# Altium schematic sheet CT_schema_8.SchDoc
size 372 x 336 mm
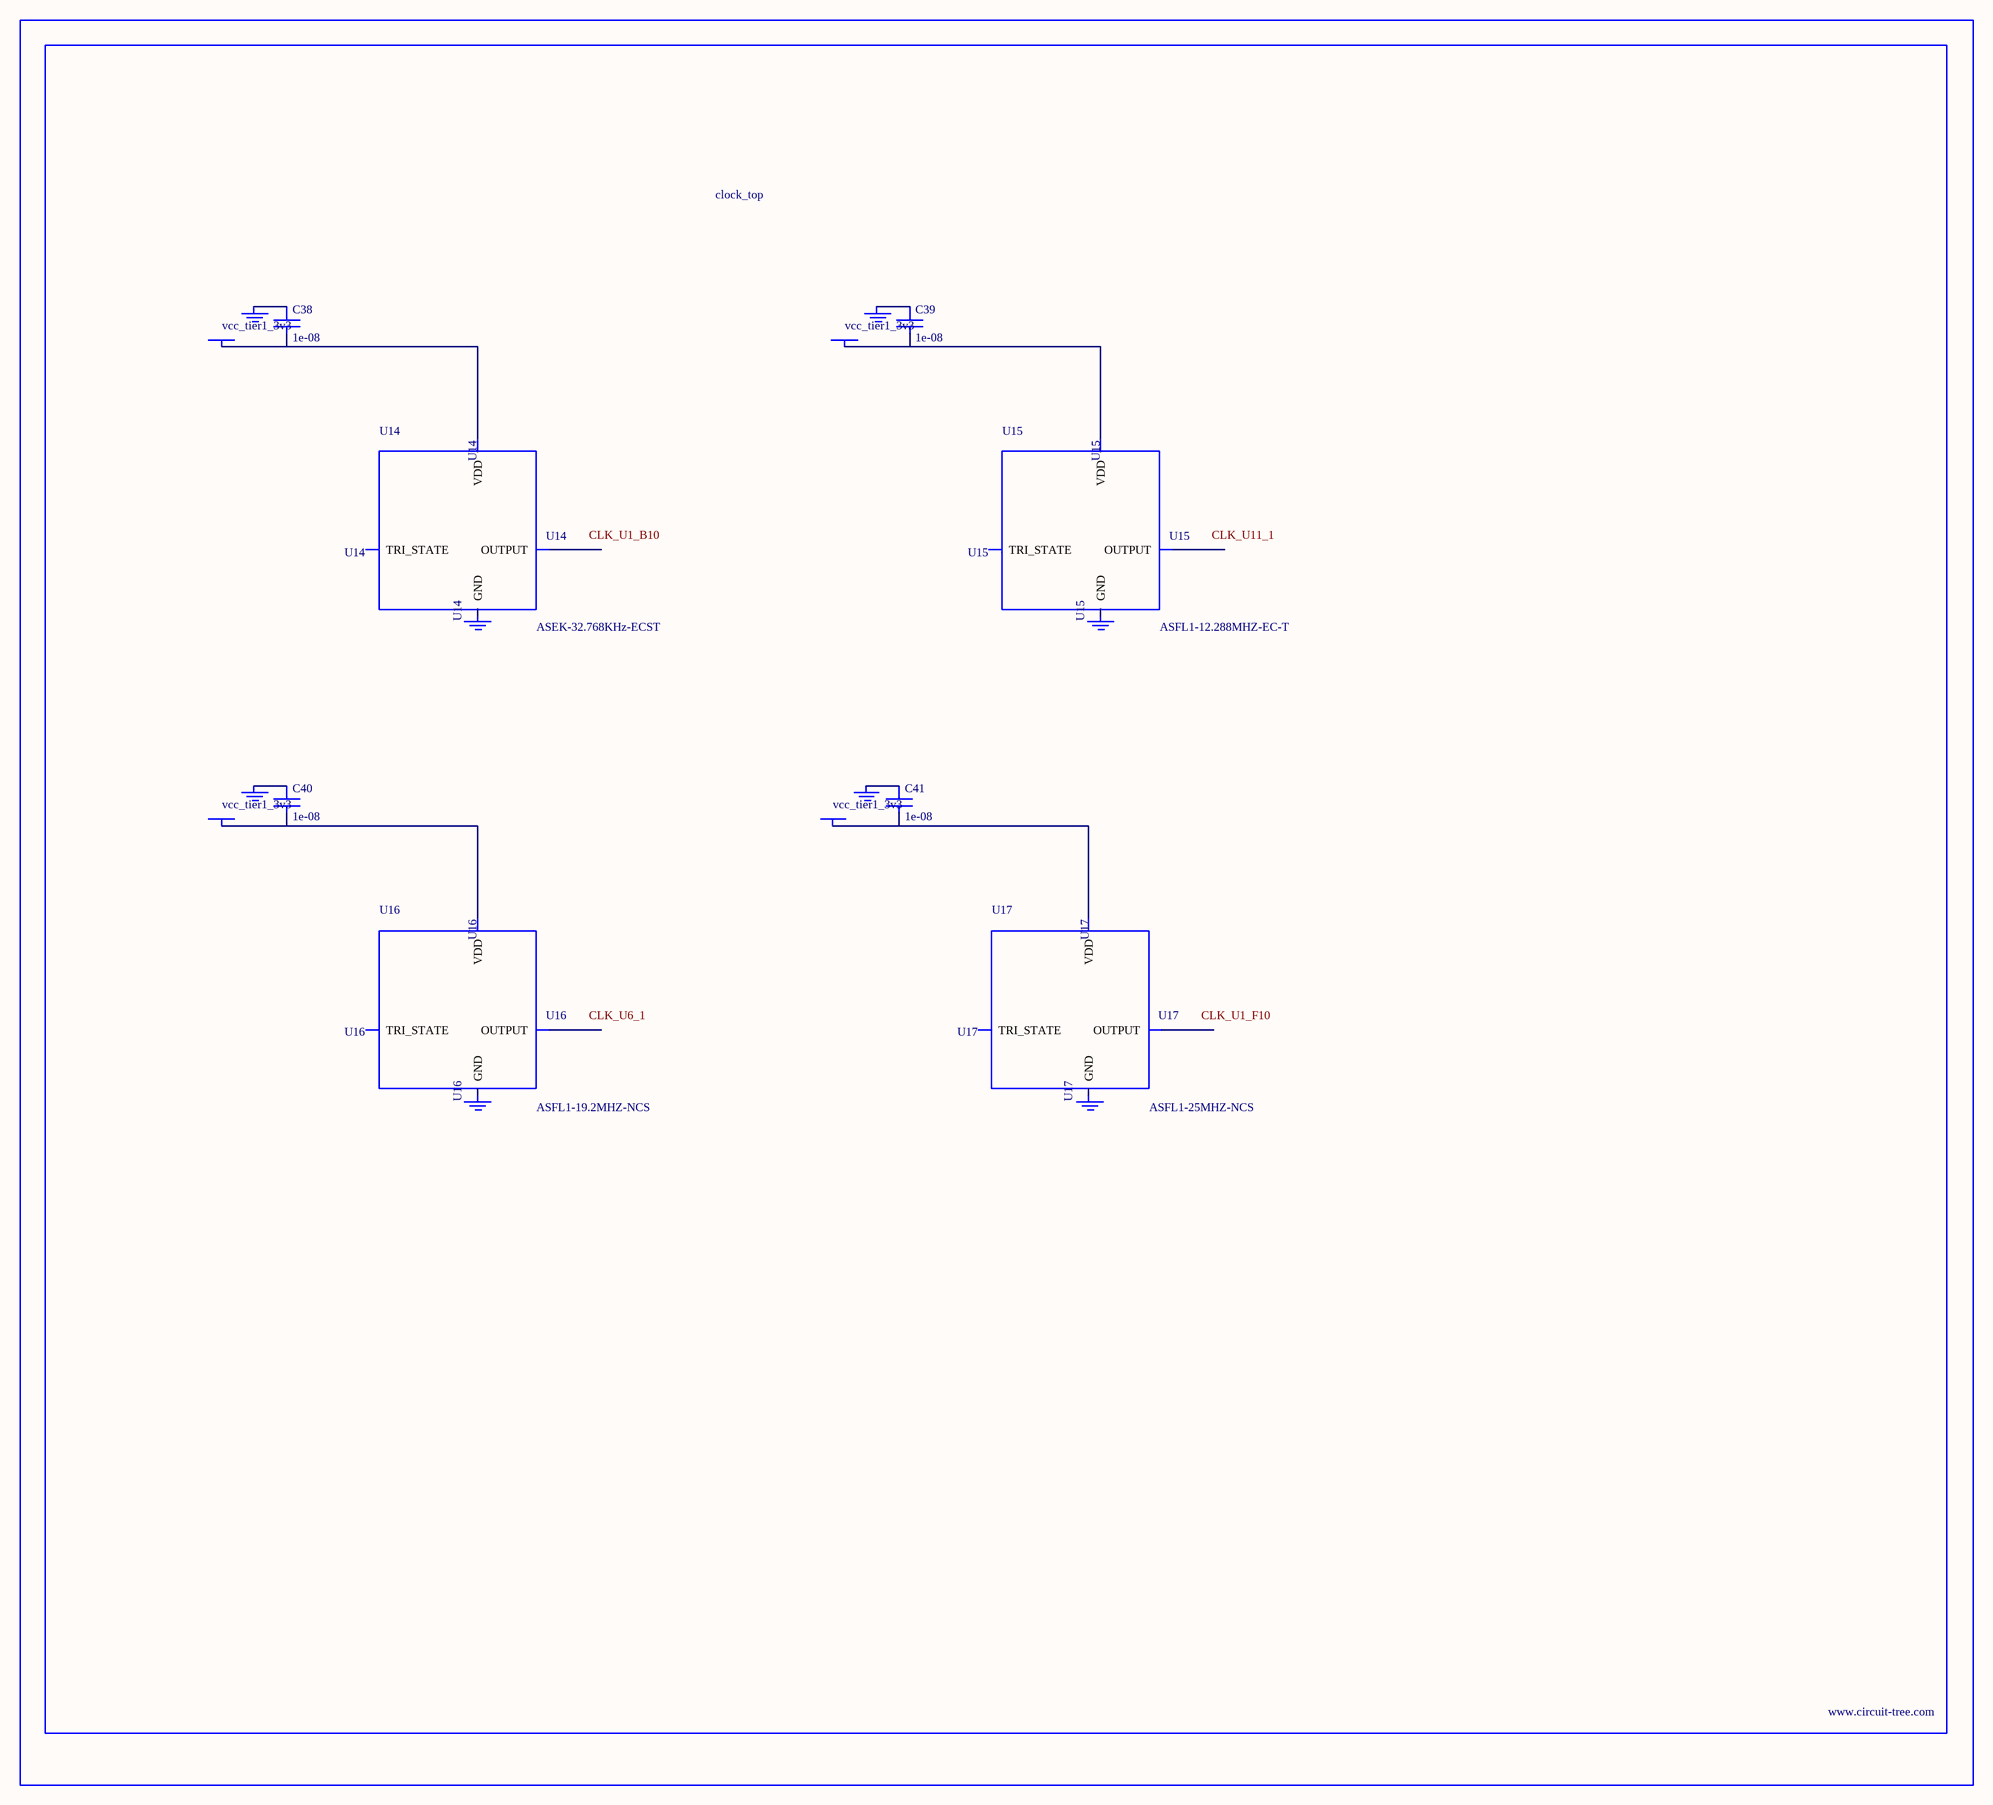
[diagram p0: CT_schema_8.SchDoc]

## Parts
BORDER7  (no value)
C38  1e-08  [C0402]
C39  1e-08  [C0402]
C40  1e-08  [C0402]
C41  1e-08  [C0402]
GND_INSTANCE_7_0  (no value)
GND_INSTANCE_7_1  (no value)
GND_INSTANCE_7_2  (no value)
GND_INSTANCE_7_3  (no value)
GND_INSTANCE_7_4  (no value)
GND_INSTANCE_7_5  (no value)
GND_INSTANCE_7_6  (no value)
GND_INSTANCE_7_7  (no value)
POWER_INSTANCE_7_0  vcc_tier1_3v3
POWER_INSTANCE_7_1  vcc_tier1_3v3
POWER_INSTANCE_7_2  vcc_tier1_3v3
POWER_INSTANCE_7_3  vcc_tier1_3v3
U14  ASEK-32.768KHz-ECST  [ASEK]
U15  ASFL1-12.288MHZ-EC-T  [ASFL1]
U16  ASFL1-19.2MHZ-NCS  [ASFL1]
U17  ASFL1-25MHZ-NCS  [ASFL1]

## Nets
NetC38_1: C38.1 GND_INSTANCE_7_0.0(GND)
NetC38_2: C38.2 POWER_INSTANCE_7_0.0(PWR) U14.4(VDD)
NetC39_1: C39.1 GND_INSTANCE_7_2.0(GND)
NetC39_2: C39.2 POWER_INSTANCE_7_1.0(PWR) U15.4(VDD)
NetC40_1: C40.1 GND_INSTANCE_7_4.0(GND)
NetC40_2: C40.2 POWER_INSTANCE_7_2.0(PWR) U16.4(VDD)
NetC41_1: C41.1 GND_INSTANCE_7_6.0(GND)
NetC41_2: C41.2 POWER_INSTANCE_7_3.0(PWR) U17.4(VDD)

Not connected (* = marked no-connect by the designer): GND_INSTANCE_7_1 0(GND); GND_INSTANCE_7_3 0(GND); GND_INSTANCE_7_5 0(GND); GND_INSTANCE_7_7 0(GND); U14 1(TRI_STATE) 2(GND) 3(OUTPUT); U15 1(TRI_STATE) 2(GND) 3(OUTPUT); U16 1(TRI_STATE) 2(GND) 3(OUTPUT); U17 1(TRI_STATE) 2(GND) 3(OUTPUT)

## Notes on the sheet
- Labels drawn without touching a wire or pin: CLK_U1_B10, CLK_U1_F10, CLK_U6_1, CLK_U11_1

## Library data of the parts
BORDER7 = BORDER_PAGE7
C38-C41 = C0402C103K3RAC
GND_INSTANCE_7_0-GND_INSTANCE_7_7 = GND
POWER_INSTANCE_7_0-POWER_INSTANCE_7_3 = PWR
